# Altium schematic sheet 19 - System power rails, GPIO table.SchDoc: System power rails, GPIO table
size A3; PageSetup: Record=PageOptions¦CenterHorizontal=True¦CenterVertical=True¦PrintScale=1.01¦XCorrection=1.00¦YCorrection=1.00¦PrintKind=0¦BorderSize=5000000¦LeftOffset=0¦BottomOffset=0¦Orientation=2¦PaperLength=4200¦PaperWidth=2970¦Scale=100¦PaperSource=15¦PrintQuality=600¦MediaType=1¦DitherType=10¦PrintScaleMode=1¦PaperKind=A3¦PaperIndex=8; Author: Juan Anzola; SheetNumber: 19; SheetTotal: 20
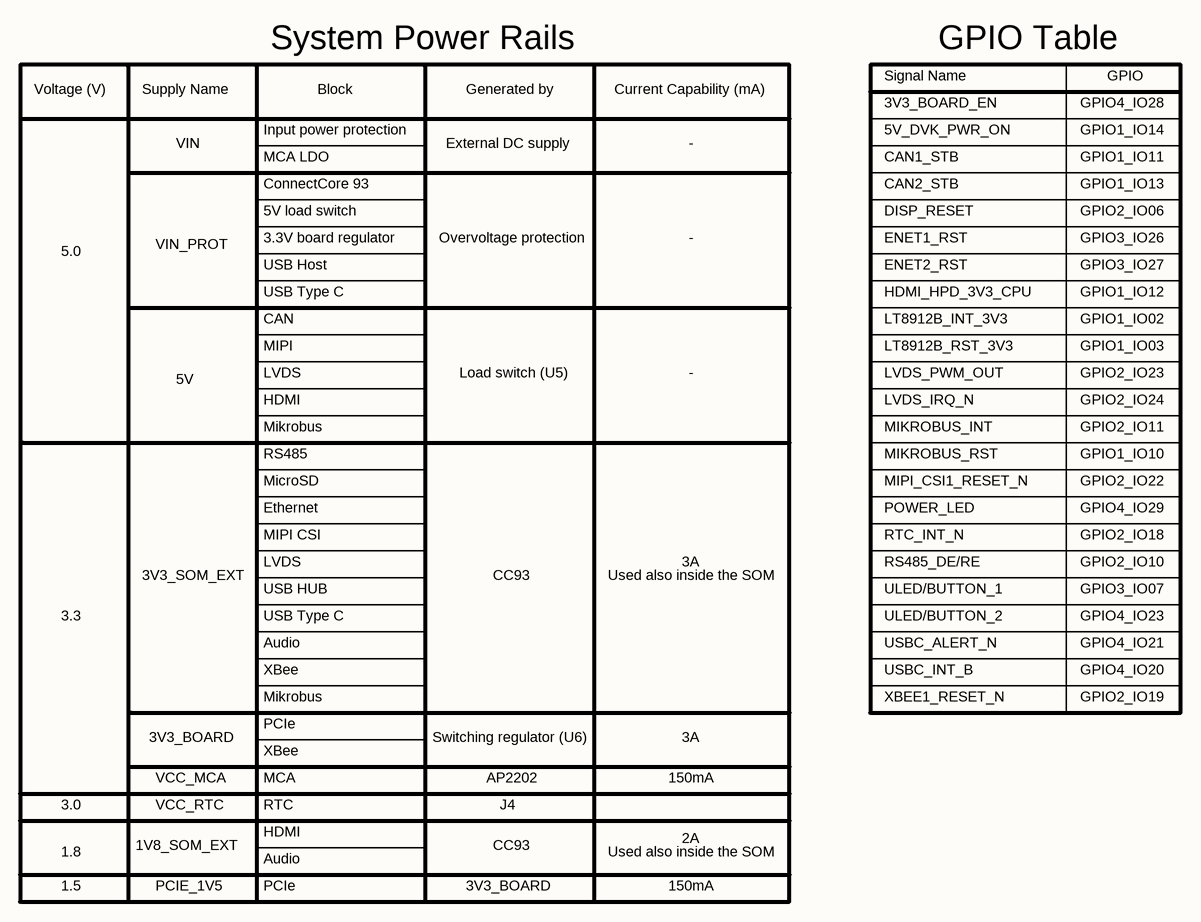
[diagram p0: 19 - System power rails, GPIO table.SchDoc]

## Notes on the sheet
- Voltage (V)
- Supply Name
- System Power Rails
- Block
- Generated by
- Current Capability (mA)
- Signal Name
- GPIO Table
- GPIO
- VIN
- Input power protection
- External DC supply
- -
- 3V3_BOARD_EN
- 5V_DVK_PWR_ON
- GPIO1_IO14
- GPIO4_IO28
- MCA LDO
- ConnectCore 93
- 5V load switch
- CAN1_STB
- CAN2_STB
- DISP_RESET
- GPIO1_IO13
- GPIO1_IO11
- GPIO2_IO06
- 5.0
- VIN_PROT
- USB Host
- 3.3V board regulator
- Overvoltage protection
- ENET1_RST
- ENET2_RST
- GPIO3_IO26
- GPIO3_IO27
- USB Type C
- CAN
- MIPI
- LT8912B_INT_3V3
- HDMI_HPD_3V3_CPU
- LT8912B_RST_3V3
- GPIO1_IO02
- GPIO1_IO03
- GPIO1_IO12
- 5V
- HDMI
- LVDS
- Load switch (U5)
- LVDS_PWM_OUT
- LVDS_IRQ_N
- GPIO2_IO24
- GPIO2_IO23
- MicroSD
- Mikrobus
- RS485
- MIPI_CSI1_RESET_N
- MIKROBUS_INT
- MIKROBUS_RST
- GPIO2_IO22
- GPIO2_IO11
- GPIO1_IO10
- Ethernet
- MIPI CSI
- POWER_LED
- RTC_INT_N
- GPIO4_IO29
- GPIO2_IO18
- 3.3
- 3V3_SOM_EXT
- USB HUB
- CC93
- Used also inside the SOM
- 3A
- ULED/BUTTON_1
- RS485_DE/RE
- ULED/BUTTON_2
- GPIO2_IO10
- GPIO3_IO07
- GPIO4_IO23
- Audio
- XBee
- USBC_ALERT_N
- USBC_INT_B
- GPIO4_IO21
- GPIO4_IO20
- 3V3_BOARD
- PCIe
- Switching regulator (U6)
- XBEE1_RESET_N
- GPIO2_IO19
- 3.0
- VCC_MCA
- VCC_RTC
- MCA
- RTC
- AP2202
- J4
- 150mA
- 1.8
- 1.5
- 1V8_SOM_EXT
- PCIE_1V5
- 2A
